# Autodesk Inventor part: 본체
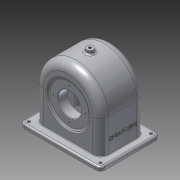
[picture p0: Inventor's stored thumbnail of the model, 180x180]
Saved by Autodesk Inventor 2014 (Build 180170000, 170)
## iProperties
Created: 2016-02
Part Number: 본체
Material: 알루미늄 6061
Document SubType Name: Modeling
Designer: Owner
Density: 2.71 g/cm^3
Appearance: 알루미늄 - 평지
Mass: 757.291 g
Surface Area: 1005.83 cm^2
Volume: 279.443 cm^3
Author: Owner
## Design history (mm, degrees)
sketch "스케치1"
  geometry: L1 (-57, 0)-(-57, -64); L2 (-57, -64)-(57, -64); L3 (57, -64)-(57, 0); A1 r 57 centre (0, 0) between (57, 0) and (-57, 0); 1 further point
  constraints: 6 end point, 2 point on circle, 2 tangent, 1 centre point, 1 coincident, 1 horizontal, 1 parallel, 1 vertical
  dimensions: "d0" = 57 radius of A1; "d1" = 64 distance from line of point (0, 0) L2
extrude "돌출1" new body sketch "스케치1" stored distance "d2" = 77; taper "d3" = 0 deg
fillet "모깎기1" dims "d4" = 14
feature "쉘1" dims "d5" = 5
sketch "스케치2"
  geometry: L1 (-43, -64)-(43, -64) reference; C1 r 31 at (0, -4); A1 r 43 centre (0, 0) between (43, 0) and (-43, 0) reference
  constraints: 1 centre point, 1 vertical alignment
  dimensions: "d6" = 31 radius of C1; "d7" = 60 distance from line of L1 C1.centre
extrude "돌출2" join sketch "스케치2" distance "d8" = 10; taper "d9" = 0 deg
sketch "스케치3"
  geometry: L1 (-64, 33.5)-(0, 33.5) reference; L2 (-4, 38.5)-(-4, 19.5); L3 (-64, -24.5)-(-64, 24.5) reference; L4 (0, 33.5)-(43, 33.5) reference; L5 (-4, 19.5)-(24, 19.5); L6 (24, 19.5)-(35.747, 33.5); L7 (0, 38.5)-(43, 38.5) reference; L8 (33.416, 38.5)-(30.899, 35.5); L9 (30.899, 35.5)-(-4, 35.5); L10 (35.747, 33.5)-(33.416, 38.5); L11 (-64, 38.5)-(0, 38.5) reference; L12 (33.416, 38.5)-(-4, 38.5); 1 further point
  constraints: 14 end point, 4 point on line, 2 parallel, 1 collinear, 1 perpendicular
  dimensions: "d10" = 60 distance between parallel lines of L3 L2; "d17" = 3 distance between parallel lines of L7 L9; "d18" = 16 distance between parallel lines of L5 L9; "d19" = 50 deg angle of L5 L6; "d20" = 5 distance between parallel lines of L8 L6; "d21" = 56 diameter of L5.end L2
revolve "회전1" stored, may be unused: angle "d23" = 90 deg
revolve "회전2" stored, may be unused: angle "d24" = 90 deg
hole "구멍1" diameter "d27" = 40; stored, may be unused: countersink angle "d31" = 90 deg, drill point angle "d33" = 118 deg; dims "d25" = 10, "d26" = 10, "d28" = 6, "d29" = 4, "d30" = 2, "d32" = 8
sketch "스케치4"
  geometry: L1 (100, -63)-(100, -14) reference; L2 (0, 0)-(86, 0) reference; L3 (-14, -63)-(-14, -14) reference; L4 (86, -77)-(0, -77) reference; L5 (-27, 13.5)-(113, 13.5); L6 (113, 13.5)-(113, -90.5); L7 (113, -90.5)-(-27, -90.5); L8 (-27, -90.5)-(-27, 13.5); L9 (-27, 13.5)-(113, -90.5); L10 (113, 13.5)-(-27, -90.5); A1 r 14 centre (86, -63) between (86, -77) and (100, -63) reference; A2 r 14 centre (86, -14) between (100, -14) and (86, 0) reference; A3 r 14 centre (0, -14) between (0, 0) and (-14, -14) reference; A4 r 14 centre (0, -63) between (-14, -63) and (0, -77) reference; 1 further point
  constraints: 12 end point, 2 midpoint, 2 parallel, 1 horizontal, 1 perpendicular
  dimensions: "d34" = 140 distance of L6.end L7.end; "d35" = 104 distance of L5.end L6.end
extrude "돌출3" join sketch "스케치4" distance "d36" = 7; taper "d37" = 0 deg
hole "구멍2" diameter "d40" = 5; stored, may be unused: countersink angle "d44" = 90 deg, drill point angle "d46" = 118 deg; dims "d38" = 8, "d39" = 8, "d41" = 6, "d42" = 4, "d43" = 2, "d45" = 8
node "작업 평면1"
sketch "스케치5"
  geometry: C1 r 2.5 at (8, -8) reference; C2 r 2.5 at (8, -96) reference; C3 r 6 at (70, -52); 1 further point
  constraints: 1 centre point, 1 coincident
  dimensions: "d48" = 6 radius of C3
extrude "돌출4" join sketch "스케치5" stored distance "d49" = 0; taper "d50" = 0 deg
hole "구멍3" diameter "d53" = 4.459; stored, may be unused: countersink angle "d57" = 90 deg, drill point angle "d59" = 118 deg; dims "d51" = 10, "d52" = 10, "d54" = 6, "d55" = 4, "d56" = 2, "d58" = 8
sketch "스케치6"
  geometry: C1 r 20 at (0, 0) reference; 2 further points
  constraints: 1 vertical alignment
  dimensions: "d60" = 28 distance of point (0, 28) C1.centre
sketch "스케치7"
  geometry: C1 r 20 at (0, 0) reference; 2 further points
  constraints: 1 vertical alignment
  dimensions: "d61" = 24 distance of C1.centre point (0, 24)
hole "구멍4" sketch "스케치7" at (0, 24) diameter "d62" = 2.459; stored, may be unused: countersink angle "d66" = 90 deg, drill point angle "d68" = 118 deg; dims "d63" = 6, "d64" = 4, "d65" = 2, "d67" = 8
hole "구멍5" sketch "스케치6" diameter "d69" = 2.459; stored, may be unused: countersink angle "d73" = 90 deg, drill point angle "d75" = 118 deg; dims "d70" = 7, "d71" = 4, "d72" = 2, "d74" = 9
chamfer "모따기1" distance "d82" = 1; stored, may be unused: second distance "d83" = 2, angle "d84" = 45 deg
fillet "모깎기2" dims "d85" = 8, "d86" = 1
fillet "모깎기3" dims "d87" = 3
node "작업 평면2"
sketch "스케치8"
  geometry: L1 (-14, 0)-(-14, -56) reference; L2 (-19.5, -64)-(68.5, -64) reference; 2 further points
  constraints: 1 other
  dimensions: "d89" = 38.5 distance from line of L1 point (24.5, -34); "d90" = 30 distance from line of point (24.5, -34) L2
feature "엠보싱1" sketch "스케치8" dims "d0" = 57, "d1" = 64, "d8" = 10, "d91" = 0.5, "d92" = 0
node "솔리드1"
mirror "대칭1"
mirror "대칭2"
pattern_circular "원형 패턴1" dims angle "d77" = 360 deg
pattern_circular "원형 패턴2" dims angle "d80" = 360 deg
other parameters: "d47" = -127, "d88" = 0.5
